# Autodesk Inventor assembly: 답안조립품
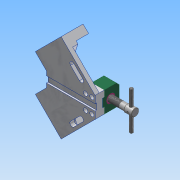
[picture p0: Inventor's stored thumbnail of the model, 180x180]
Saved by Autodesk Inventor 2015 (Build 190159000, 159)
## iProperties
Created: 2019-04
Part Number: 답안조립품
Document SubType Name: Assembly
Designer: user
Author: user
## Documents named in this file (11)
- C:\Users\user\Desktop\490407V1021\답안조립품.iam
- C:\Users\user\Desktop\490407V1021\본체.ipt
- C:\Users\user\Desktop\490407V1021\서포트.ipt
- C:\Users\user\Desktop\490407V1021\리드스크류.ipt
- C:\Users\user\Desktop\490407V1021\핸들.ipt
- C:\Users\user\Desktop\490407V1021\멈춤나사 M4x5.ipt
- C:\Users\user\Desktop\490407V1021\조.ipt
- C:\Users\user\Desktop\490407V1021\부시.ipt
- C:\Users\user\Desktop\490407V1021\평행 핀 2.5x24.ipt
- C:\Users\user\Desktop\490407V1021\멈춤나사 M4x10.ipt
- C:\Users\user\Desktop\490407V1021\볼트 M4x16.ipt
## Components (1 placed, 1 different names)
1. 핸들:1
